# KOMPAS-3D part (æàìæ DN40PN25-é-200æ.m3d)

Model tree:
1. Объединить компоненты:1  (labels: СЕНС DN40PN25-В-200С)

Referenced files in D:\Савин\!СЕНСОР\3D для заказчика\!Новый перечень\СЕНС\4. СЕНС-В-200С\DN40\: СЕНС DN40PN25-В-200С.a3d
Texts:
  СЕНС DN40PN25-В-200С
  ООО НПП Сенсор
